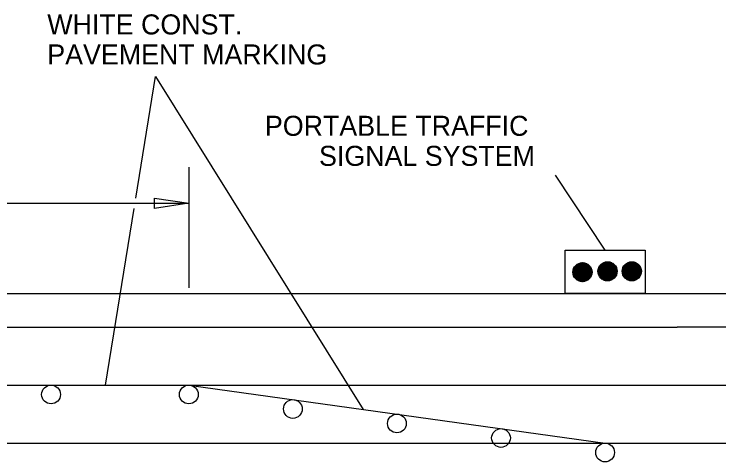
# Model space of a CAD drawing. Extents: x 1806907 to 1812607, y 675071 to 676228.
# Drawn here: x 1809449.2 to 1809660.3, y 675355.5 to 675489.6 of the extents above; entities that cross this region are included whole.
import ezdxf

# ---------------------------------------------------------------- set-up
doc = ezdxf.new("R2010")
doc.units = 0
doc.layers.add('Default', color=7, linetype='Continuous')

msp = doc.modelspace()

# ---------------------------------------------------------------- linework, layer by layer
at = {"layer": 'Default'}
for p, q in [((1809501.54, 675443.73), (1809501.54, 675407.56)), ((1809626.17, 675418.85), (1809611.33, 675441.37)), ((1809491.23, 675431.4), (1809491.23, 675434.49)), ((1809491.23, 675434.49), (1809501.54, 675432.94)), ((1809227.42, 675432.94), (1809501.54, 675432.94)), ((1809501.54, 675432.94), (1809491.23, 675431.4)), ((1809621.94, 675410.91), (1809618.04, 675414.81)), ((1809622, 675411.03), (1809618.16, 675414.87)), ((1809622.06, 675411.15), (1809618.28, 675414.93)), ((1809622.11, 675411.28), (1809618.4, 675414.98)), ((1809622.15, 675411.41), (1809618.53, 675415.03)), ((1809622.19, 675411.55), (1809618.67, 675415.07)), ((1809622.23, 675411.69), (1809618.81, 675415.1)), ((1809622.25, 675411.84), (1809618.96, 675415.13)), ((1809622.27, 675411.99), (1809619.12, 675415.15)), ((1809622.29, 675412.16), (1809619.28, 675415.16)), ((1809622.29, 675412.33), (1809619.46, 675415.16)), ((1809622.28, 675412.52), (1809619.64, 675415.16)), ((1809622.26, 675412.72), (1809619.84, 675415.13)), ((1809622.22, 675412.94), (1809620.06, 675415.09)), ((1809622.15, 675413.18), (1809620.31, 675415.02)), ((1809622.04, 675413.47), (1809620.59, 675414.91)), ((1809629.14, 675410.75), (1809625.1, 675414.8)), ((1809629.22, 675410.85), (1809625.2, 675414.87)), ((1809629.29, 675410.96), (1809625.3, 675414.94)), ((1809629.36, 675411.07), (1809625.41, 675415.01)), ((1809629.42, 675411.18), (1809625.53, 675415.08)), ((1809629.48, 675411.29), (1809625.64, 675415.14)), ((1809629.54, 675411.42), (1809625.76, 675415.19)), ((1809629.59, 675411.54), (1809625.89, 675415.24)), ((1809629.64, 675411.67), (1809626.02, 675415.29)), ((1809629.68, 675411.81), (1809626.16, 675415.33)), ((1809629.71, 675411.95), (1809626.3, 675415.36)), ((1809629.74, 675412.1), (1809626.45, 675415.39)), ((1809629.76, 675412.26), (1809626.6, 675415.41)), ((1809629.77, 675412.42), (1809626.77, 675415.42)), ((1809629.77, 675412.6), (1809626.94, 675415.43)), ((1809629.77, 675412.78), (1809627.13, 675415.42)), ((1809629.74, 675412.98), (1809627.33, 675415.4)), ((1809629.7, 675413.2), (1809627.55, 675415.35)), ((1809629.63, 675413.44), (1809627.79, 675415.29)), ((1809629.52, 675413.73), (1809628.08, 675415.17)), ((1809629.31, 675414.12), (1809628.47, 675414.96)), ((1809636.45, 675410.8), (1809632.41, 675414.83)), ((1809636.52, 675410.9), (1809632.52, 675414.9)), ((1809636.59, 675411.01), (1809632.62, 675414.98)), ((1809636.66, 675411.11), (1809632.73, 675415.04)), ((1809636.72, 675411.23), (1809632.85, 675415.1)), ((1809636.78, 675411.35), (1809632.96, 675415.16)), ((1809636.88, 675411.6), (1809633.22, 675415.27)), ((1809636.93, 675411.73), (1809633.35, 675415.31)), ((1809636.96, 675411.87), (1809633.49, 675415.35)), ((1809636.99, 675412.02), (1809633.63, 675415.38)), ((1809637.02, 675412.17), (1809633.79, 675415.4)), ((1809637.04, 675412.33), (1809633.95, 675415.42)), ((1809637.04, 675412.5), (1809634.11, 675415.43)), ((1809637.04, 675412.68), (1809634.29, 675415.43)), ((1809637.03, 675412.87), (1809634.49, 675415.41)), ((1809637, 675413.08), (1809634.69, 675415.38)), ((1809636.94, 675413.3), (1809634.92, 675415.33)), ((1809636.86, 675413.57), (1809635.18, 675415.24)), ((1809636.72, 675413.89), (1809635.5, 675415.1)), ((1809619.87, 675409.45), (1809616.58, 675412.74)), ((1809620.02, 675409.48), (1809616.6, 675412.89)), ((1809620.16, 675409.51), (1809616.64, 675413.03)), ((1809620.3, 675409.55), (1809616.68, 675413.17)), ((1809620.43, 675409.6), (1809616.72, 675413.3)), ((1809620.55, 675409.65), (1809616.77, 675413.43)), ((1809620.67, 675409.71), (1809616.83, 675413.55)), ((1809620.79, 675409.77), (1809616.89, 675413.67)), ((1809620.9, 675409.83), (1809616.96, 675413.78)), ((1809621.01, 675409.9), (1809617.02, 675413.89)), ((1809621.12, 675409.97), (1809617.1, 675413.99)), ((1809621.22, 675410.05), (1809617.17, 675414.09)), ((1809621.31, 675410.13), (1809617.25, 675414.19)), ((1809621.4, 675410.21), (1809617.34, 675414.28)), ((1809621.49, 675410.3), (1809617.43, 675414.37)), ((1809621.58, 675410.39), (1809617.52, 675414.45)), ((1809621.66, 675410.49), (1809617.62, 675414.53)), ((1809621.73, 675410.59), (1809617.72, 675414.61)), ((1809621.81, 675410.69), (1809617.82, 675414.68)), ((1809621.88, 675410.8), (1809617.93, 675414.75)), ((1809621.82, 675413.86), (1809620.98, 675414.7)), ((1809627.03, 675409.68), (1809624.03, 675412.69)), ((1809627.2, 675409.69), (1809624.04, 675412.85)), ((1809627.35, 675409.71), (1809624.06, 675413.01)), ((1809627.5, 675409.74), (1809624.09, 675413.16)), ((1809627.64, 675409.78), (1809624.12, 675413.3)), ((1809627.78, 675409.82), (1809624.16, 675413.43)), ((1809627.91, 675409.86), (1809624.21, 675413.57)), ((1809628.04, 675409.91), (1809624.26, 675413.69)), ((1809628.16, 675409.97), (1809624.32, 675413.81)), ((1809628.28, 675410.03), (1809624.38, 675413.93)), ((1809628.39, 675410.09), (1809624.44, 675414.04)), ((1809628.5, 675410.16), (1809624.51, 675414.15)), ((1809628.6, 675410.23), (1809624.58, 675414.25)), ((1809628.7, 675410.31), (1809624.66, 675414.35)), ((1809628.8, 675410.39), (1809624.74, 675414.45)), ((1809628.89, 675410.48), (1809624.82, 675414.54)), ((1809628.98, 675410.57), (1809624.91, 675414.63)), ((1809629.06, 675410.66), (1809625, 675414.71)), ((1809634.38, 675409.69), (1809631.3, 675412.76)), ((1809634.54, 675409.7), (1809631.32, 675412.92)), ((1809634.69, 675409.73), (1809631.34, 675413.07)), ((1809634.84, 675409.76), (1809631.37, 675413.22)), ((1809634.98, 675409.79), (1809631.41, 675413.36)), ((1809635.11, 675409.84), (1809631.45, 675413.49)), ((1809635.24, 675409.88), (1809631.5, 675413.62)), ((1809635.36, 675409.94), (1809631.55, 675413.75)), ((1809635.48, 675409.99), (1809631.61, 675413.86)), ((1809635.6, 675410.06), (1809631.67, 675413.98)), ((1809635.71, 675410.12), (1809631.74, 675414.09)), ((1809635.81, 675410.19), (1809631.81, 675414.2)), ((1809635.91, 675410.27), (1809631.89, 675414.3)), ((1809636.01, 675410.35), (1809631.96, 675414.4)), ((1809636.11, 675410.43), (1809632.05, 675414.49)), ((1809636.2, 675410.52), (1809632.13, 675414.58)), ((1809636.28, 675410.61), (1809632.22, 675414.67)), ((1809636.37, 675410.7), (1809632.32, 675414.75)), ((1809636.33, 675414.45), (1809636.06, 675414.72)), ((1809619.55, 675409.42), (1809616.54, 675412.42)), ((1809619.37, 675409.42), (1809616.54, 675412.25)), ((1809619.19, 675409.42), (1809616.55, 675412.06)), ((1809619.71, 675409.43), (1809616.56, 675412.59)), ((1809618.99, 675409.45), (1809616.57, 675411.86)), ((1809618.77, 675409.49), (1809616.61, 675411.64)), ((1809618.53, 675409.56), (1809616.68, 675411.4)), ((1809618.24, 675409.67), (1809616.79, 675411.11)), ((1809617.85, 675409.88), (1809617, 675410.72)), ((1809626.86, 675409.68), (1809624.03, 675412.51)), ((1809626.67, 675409.69), (1809624.03, 675412.33)), ((1809626.47, 675409.71), (1809624.06, 675412.13)), ((1809626.26, 675409.75), (1809624.1, 675411.91)), ((1809626.01, 675409.82), (1809624.17, 675411.66)), ((1809625.72, 675409.93), (1809624.28, 675411.38)), ((1809625.33, 675410.14), (1809624.49, 675410.99)), ((1809634.21, 675409.68), (1809631.3, 675412.59)), ((1809634.03, 675409.68), (1809631.3, 675412.41)), ((1809633.83, 675409.7), (1809631.31, 675412.22)), ((1809633.62, 675409.73), (1809631.35, 675412.01)), ((1809633.39, 675409.79), (1809631.4, 675411.78)), ((1809633.13, 675409.87), (1809631.49, 675411.51)), ((1809632.8, 675410.03), (1809631.64, 675411.18)), ((1809377.42, 675405.86), (1810285.94, 675405.86)), ((1809377.42, 675395.86), (1809647.71, 675395.86)), ((1809809.88, 675395.86), (1809647.71, 675395.86)), ((1809227.42, 675378.48), (1809748.63, 675378.48)), ((1809501.54, 675378.48), (1809626.17, 675361.1)), ((1809377.42, 675361.1), (1809502.12, 675361.1)), ((1809502.12, 675361.1), (1809747.96, 675361.1))]:
    msp.add_line(p, q, dxfattribs=at)
for points in [[(1809485.65, 675434.49), (1809491.52, 675470.93), (1809553.76, 675371.2)], [(1809476.61, 675378.48), (1809485.15, 675431.4)], [(1809227.42, 675378.48), (1809501.54, 675378.48)]]:
    msp.add_lwpolyline(points, dxfattribs=at)
msp.add_lwpolyline([(1809614.18, 675405.86), (1809614.18, 675418.85), (1809638.16, 675418.85), (1809638.16, 675405.86)], close=True, dxfattribs=at)
for centre, radius in [((1809619.41, 675412.29), 2.87), ((1809626.9, 675412.55), 2.87), ((1809634.17, 675412.55), 2.87), ((1809460.29, 675375.67), 2.81), ((1809501.54, 675375.67), 2.81), ((1809532.7, 675371.32), 2.81), ((1809563.85, 675366.98), 2.81), ((1809595.01, 675362.63), 2.81), ((1809626.17, 675358.28), 2.81)]:
    msp.add_circle(centre, radius, dxfattribs=at)

# ---------------------------------------------------------------- texts
for s, p in [('WHITE CONST.', (1809459.17, 675483.48)), ('PAVEMENT MARKING', (1809459.17, 675474.48)), ('PORTABLE TRAFFIC', (1809524.33, 675453.12)), ('SIGNAL SYSTEM', (1809540.53, 675444.12))]:
    msp.add_text(s, height=6, dxfattribs=at).set_placement(p)

doc.saveas('drawing.dxf')
